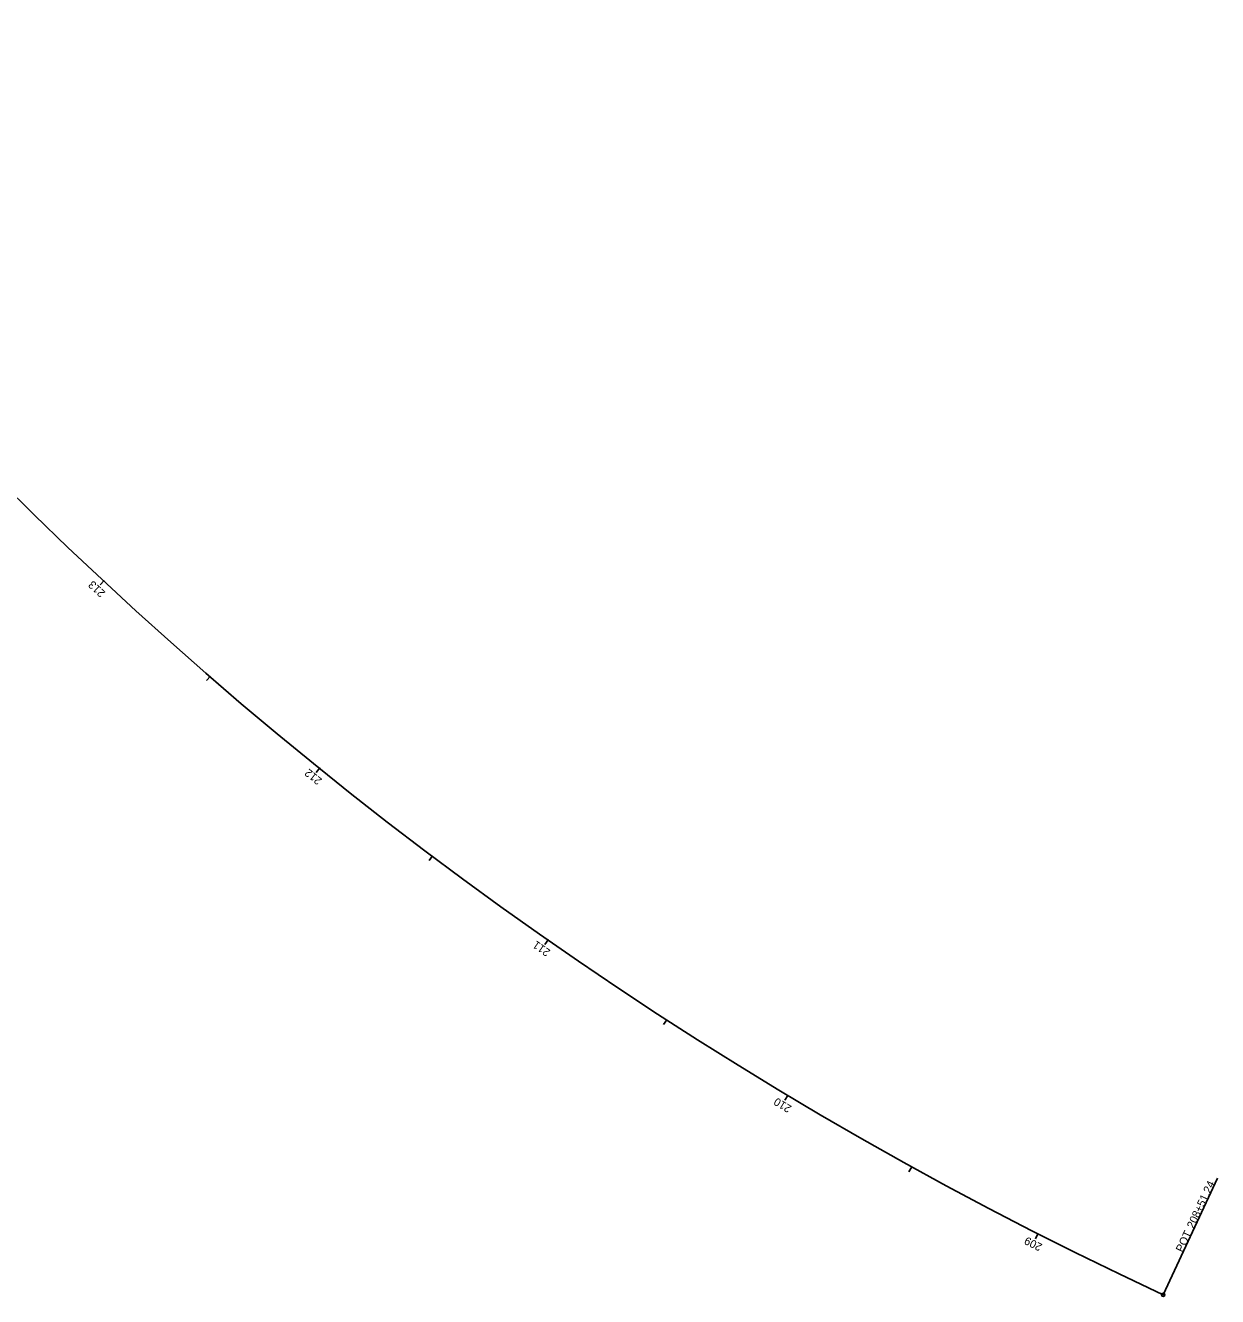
# Model space of a CAD drawing. Extents: x 1454426 to 1455277, y 587472 to 590476.
# Drawn here: x 1454859.5 to 1455276.6, y 587471.9 to 587916.7 of the extents above; entities that cross this region are included whole.
import ezdxf

# ---------------------------------------------------------------- set-up
doc = ezdxf.new("R2010")
doc.units = 0
for name, color, linetype in [('Default', 7, 'Continuous'), ('GT_Target_Soil_Boring', 7, 'Continuous'), ('PV_P_Saw_Cut_Line', 7, 'Continuous'), ('SC_Scratch1', 7, 'Continuous'), ('SC_Scratch2', 7, 'Continuous'), ('SC_Scratch3', 7, 'Continuous')]:
    doc.layers.add(name, color=color, linetype=linetype)

msp = doc.modelspace()

# ---------------------------------------------------------------- linework, layer by layer
at = {"layer": 'Default'}
for centre in [(1454887.03, 587722.43), (1454887.03, 587722.43), (1454887.03, 587722.43), (1454962.52, 587656.88), (1454962.52, 587656.88), (1454962.52, 587656.88), (1455042.4, 587596.75), (1455042.4, 587596.75), (1455042.4, 587596.75), (1455126.27, 587542.34), (1455126.27, 587542.34), (1455126.27, 587542.34), (1455213.74, 587493.91), (1455213.74, 587493.91), (1455213.74, 587493.91), (1455257.57, 587472.54), (1455257.57, 587472.54), (1455257.57, 587472.54)]:
    msp.add_circle(centre, 0.0000833, dxfattribs=at)
at = {"layer": 'GT_Target_Soil_Boring'}
msp.add_arc((1455863.38, 588770.51), 1432.39, 161.3175, 244.97965, dxfattribs=at)
at = {"layer": 'PV_P_Saw_Cut_Line'}
msp.add_arc((1455863.38, 588770.51), 1432.39, 161.3175, 244.97965, dxfattribs=at)
at = {"layer": 'SC_Scratch1'}
for p, q in [((1454887.03, 587722.43), (1454885.67, 587720.97)), ((1454924.2, 587688.99), (1454922.89, 587687.48)), ((1454962.52, 587656.88), (1454961.26, 587655.32)), ((1455001.93, 587626.12), (1455000.73, 587624.52)), ((1455042.4, 587596.75), (1455041.25, 587595.11)), ((1455083.86, 587568.81), (1455082.77, 587567.13)), ((1455126.27, 587542.34), (1455125.25, 587540.62)), ((1455169.59, 587517.36), (1455168.62, 587515.61)), ((1455257.57, 587472.54), (1455276.6, 587513.32)), ((1455213.74, 587493.91), (1455212.84, 587492.13))]:
    msp.add_line(p, q, dxfattribs=at)
msp.add_circle((1455257.57, 587472.54), 0.6, dxfattribs=at)
at = {"layer": 'SC_Scratch2'}
for p, q in [((1454887.03, 587722.43), (1454885.67, 587720.97)), ((1454924.2, 587688.99), (1454922.89, 587687.48)), ((1454962.52, 587656.88), (1454961.26, 587655.32)), ((1455001.93, 587626.12), (1455000.73, 587624.52)), ((1455042.4, 587596.75), (1455041.25, 587595.11)), ((1455083.86, 587568.81), (1455082.77, 587567.13)), ((1455126.27, 587542.34), (1455125.25, 587540.62)), ((1455169.59, 587517.36), (1455168.62, 587515.61)), ((1455257.57, 587472.54), (1455276.6, 587513.32)), ((1455213.74, 587493.91), (1455212.84, 587492.13))]:
    msp.add_line(p, q, dxfattribs=at)
msp.add_circle((1455257.57, 587472.54), 0.6, dxfattribs=at)
at = {"layer": 'SC_Scratch3'}
for p, q in [((1454887.03, 587722.43), (1454885.67, 587720.97)), ((1454924.2, 587688.99), (1454922.89, 587687.48)), ((1454962.52, 587656.88), (1454961.26, 587655.32)), ((1455001.93, 587626.12), (1455000.73, 587624.52)), ((1455042.4, 587596.75), (1455041.25, 587595.11)), ((1455083.86, 587568.81), (1455082.77, 587567.13)), ((1455126.27, 587542.34), (1455125.25, 587540.62)), ((1455169.59, 587517.36), (1455168.62, 587515.61)), ((1455257.57, 587472.54), (1455276.6, 587513.32)), ((1455213.74, 587493.91), (1455212.84, 587492.13))]:
    msp.add_line(p, q, dxfattribs=at)
msp.add_circle((1455257.57, 587472.54), 0.6, dxfattribs=at)

# ---------------------------------------------------------------- texts
at = {"layer": 'SC_Scratch1'}
for s, rotation, p in [('213', 137.0292, (1454887.68, 587718.34)), ('212', 141.0292, (1454963.49, 587652.87)), ('211', 145.0292, (1455043.39, 587593)), ('210', 149.0292, (1455127.78, 587538.47)), ('208+51.24', 64.9796, (1455268.22, 587495.48)), ('POT', 64.9796, (1455264.36, 587487.21)), ('209', 153.0292, (1455215.49, 587490.17))]:
    msp.add_text(s, height=2.8, rotation=rotation, dxfattribs=at).set_placement(p)
at = {"layer": 'SC_Scratch2'}
for s, rotation, p in [('213', 137.0292, (1454887.68, 587718.34)), ('212', 141.0292, (1454963.49, 587652.87)), ('211', 145.0292, (1455043.39, 587593)), ('210', 149.0292, (1455127.78, 587538.47)), ('208+51.24', 64.9796, (1455268.22, 587495.48)), ('POT', 64.9796, (1455264.36, 587487.21)), ('209', 153.0292, (1455215.49, 587490.17))]:
    msp.add_text(s, height=2.8, rotation=rotation, dxfattribs=at).set_placement(p)
at = {"layer": 'SC_Scratch3'}
for s, rotation, p in [('213', 137.0292, (1454887.68, 587718.34)), ('212', 141.0292, (1454963.49, 587652.87)), ('211', 145.0292, (1455043.39, 587593)), ('210', 149.0292, (1455127.78, 587538.47)), ('208+51.24', 64.9796, (1455268.22, 587495.48)), ('POT', 64.9796, (1455264.36, 587487.21)), ('209', 153.0292, (1455215.49, 587490.17))]:
    msp.add_text(s, height=2.8, rotation=rotation, dxfattribs=at).set_placement(p)

doc.saveas('drawing.dxf')
